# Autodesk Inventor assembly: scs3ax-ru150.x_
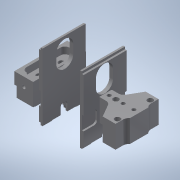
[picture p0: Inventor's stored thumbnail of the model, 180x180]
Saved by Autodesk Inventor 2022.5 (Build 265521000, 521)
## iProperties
Part Number: scs3ax-ru150.x_
Material: 一般
Document SubType Name: Assembly
Designer: ImaoCorp
Sending System: SOLIDWORKS 2017-2017317
MC: AMD64
MC_MODEL: Intel64 Family 6 Model 60 Stepping 3, GenuineIntel
OS: Windows_NT
FRU: Parasolid Version 29.0, build 201,  4-17-2017
FORMAT: text
GUISE: transmit
KEY: scs3ax-ru150
FILE: scs3ax-ru150.x_t
DATE: Wed Sep 18 16:20:02 2019
Author: ImaoCorp
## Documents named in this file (5)
- X:\14_SW2022-Inv2022\00_全2023-1023新製品(TCC)まで\s\scs3ax-ru150\SCS3AX-RU150.iam
- X:\14_SW2022-Inv2022\00_全2023-1023新製品(TCC)まで\s\scs3ax-ru150\scs3ax-ru150_01.ipt
- X:\14_SW2022-Inv2022\00_全2023-1023新製品(TCC)まで\s\scs3ax-ru150\scs3ax-ru150_02.ipt
- X:\14_SW2022-Inv2022\00_全2023-1023新製品(TCC)まで\s\scs3ax-ru150\scs3ax-ru150_03.ipt
- X:\14_SW2022-Inv2022\00_全2023-1023新製品(TCC)まで\s\scs3ax-ru150\scs3ax-ru150_04.ipt
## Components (4 placed, 4 different names)
1. scs3ax-ru150_01
2. scs3ax-ru150_02
3. scs3ax-ru150_03
4. scs3ax-ru150_04
